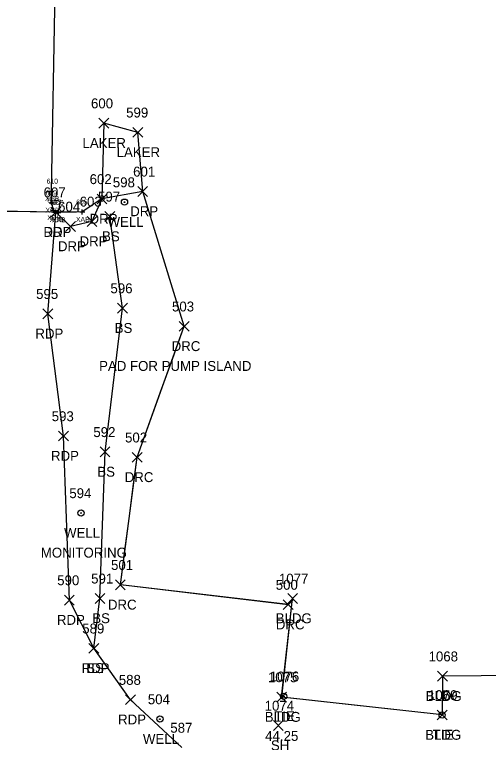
# Model space of a CAD drawing. Extents: x 1715662 to 1717487, y 887396 to 890004.
# Drawn here: x 1716620 to 1716715.7, y 888252.4 to 888399.3 of the extents above; entities that cross this region are included whole.
import ezdxf

# ---------------------------------------------------------------- set-up
doc = ezdxf.new("R2010")
doc.units = 0
for name, color, linetype in [('B_A', 7, 'Continuous'), ('B_I', 7, 'Continuous'), ('B_TIC', 7, 'Continuous'), ('BDC', 7, 'Continuous'), ('BSUBM', 7, 'Continuous'), ('C_A', 7, 'Continuous'), ('C_C', 7, 'Continuous'), ('C_I', 7, 'Continuous'), ('CBP', 7, 'Continuous'), ('L_A', 7, 'Continuous'), ('L_I', 7, 'Continuous'), ('L_TIC', 7, 'Continuous'), ('LAWE', 7, 'Continuous'), ('LBC', 7, 'Continuous'), ('LELB', 7, 'Continuous'), ('LSOGP', 7, 'Continuous'), ('P_A', 7, 'Continuous'), ('P_I', 7, 'Continuous'), ('P_TIC', 7, 'Continuous'), ('PET', 7, 'Continuous'), ('R_A', 7, 'Continuous'), ('R_C', 7, 'Continuous'), ('R_I', 7, 'Continuous'), ('R_TIC', 7, 'Continuous'), ('RDP', 7, 'Continuous'), ('U_A', 7, 'Continuous'), ('U_C', 7, 'Continuous'), ('U_I', 7, 'Continuous'), ('UWW', 7, 'Continuous')]:
    doc.layers.add(name, color=color, linetype=linetype)

msp = doc.modelspace()

# ---------------------------------------------------------------- linework, layer by layer
at = {"layer": 'B_TIC'}
for p, q in [((1716627.47, 888363.71), (1716627.55, 888363.71)), ((1716627.55, 888361.33), (1716627.62, 888361.33)), ((1716627.88, 888359.84), (1716627.96, 888359.84)), ((1716628.39, 888359.45), (1716628.47, 888359.45)), ((1716628.91, 888359.4), (1716628.98, 888359.4)), ((1716633.73, 888359.48), (1716633.8, 888359.48))]:
    msp.add_line(p, q, dxfattribs=at)
for points in [[(1716626.97, 888363.71), (1716627.97, 888363.71)], [(1716627.47, 888363.21), (1716627.47, 888364.21)], [(1716627.55, 888360.83), (1716627.55, 888361.83)], [(1716627.05, 888361.33), (1716628.05, 888361.33)], [(1716627.88, 888359.34), (1716627.88, 888360.34)], [(1716627.38, 888359.84), (1716628.38, 888359.84)], [(1716627.89, 888359.45), (1716628.89, 888359.45)], [(1716628.39, 888358.95), (1716628.39, 888359.95)], [(1716628.4, 888359.4), (1716629.4, 888359.4)], [(1716628.9, 888358.9), (1716628.9, 888359.9)], [(1716633.22, 888359.48), (1716634.22, 888359.48)], [(1716633.72, 888358.98), (1716633.72, 888359.98)]]:
    msp.add_lwpolyline(points, dxfattribs=at)
at = {"layer": 'BDC'}
msp.add_lwpolyline([(1716628.39, 888359.45), (1716627.88, 888359.84), (1716627.55, 888361.33), (1716627.47, 888363.71), (1716628.25, 888404.24), (1716628.98, 888438.57)], dxfattribs=at)
at = {"layer": 'BSUBM'}
msp.add_lwpolyline([(1716633.72, 888359.48), (1716628.9, 888359.4)], dxfattribs=at)
at = {"layer": 'CBP'}
for centre, radius in [((1716674.39, 888261.7), 0.625), ((1716674.39, 888261.7), 0.0833), ((1716706.38, 888257.94), 0.625), ((1716706.38, 888257.94), 0.0833)]:
    msp.add_circle(centre, radius, dxfattribs=at)
at = {"layer": 'L_TIC'}
for points in [[(1716637.05, 888376.41), (1716639.05, 888378.41)], [(1716639.05, 888376.41), (1716637.05, 888378.41)], [(1716643.94, 888374.56), (1716645.94, 888376.56)], [(1716645.94, 888374.56), (1716643.94, 888376.56)], [(1716638.26, 888357.58), (1716640.26, 888359.58)], [(1716640.26, 888357.58), (1716638.26, 888359.58)], [(1716640.82, 888339.07), (1716642.82, 888341.07)], [(1716642.82, 888339.07), (1716640.82, 888341.07)], [(1716637.31, 888310.04), (1716639.31, 888312.04)], [(1716639.31, 888310.04), (1716637.31, 888312.04)], [(1716636.29, 888280.47), (1716638.29, 888282.47)], [(1716638.29, 888280.47), (1716636.29, 888282.47)], [(1716675.19, 888280.45), (1716677.19, 888282.45)], [(1716677.19, 888280.45), (1716675.19, 888282.45)], [(1716635.07, 888270.39), (1716637.07, 888272.39)], [(1716637.07, 888270.39), (1716635.07, 888272.39)], [(1716705.46, 888264.75), (1716707.46, 888266.75)], [(1716707.46, 888264.75), (1716705.46, 888266.75)], [(1716672.97, 888260.55), (1716674.97, 888262.55)], [(1716674.97, 888260.55), (1716672.97, 888262.55)], [(1716705.37, 888256.93), (1716707.37, 888258.93)], [(1716707.37, 888256.93), (1716705.37, 888258.93)], [(1716672.31, 888254.8), (1716674.31, 888256.8)], [(1716674.31, 888254.8), (1716672.31, 888256.8)]]:
    msp.add_lwpolyline(points, dxfattribs=at)
at = {"layer": 'LAWE'}
msp.add_lwpolyline([(1716644.94, 888375.56), (1716638.05, 888377.41)], dxfattribs=at)
at = {"layer": 'LBC'}
msp.add_lwpolyline([(1716706.46, 888265.75), (1716706.37, 888257.93), (1716673.97, 888261.55), (1716676.19, 888281.45)], dxfattribs=at)
at = {"layer": 'LELB'}
msp.add_lwpolyline([(1716636.07, 888271.39), (1716637.29, 888281.47), (1716638.31, 888311.04), (1716641.82, 888340.07), (1716639.26, 888358.58)], dxfattribs=at)
at = {"layer": 'LSOGP'}
msp.add_lwpolyline([(1716722.06, 888265.93), (1716706.46, 888265.74), (1716706.38, 888257.93), (1716673.98, 888261.56), (1716676.19, 888281.45), (1716675.31, 888280.2), (1716666.83, 888281.21), (1716658.35, 888282.21), (1716649.88, 888283.21), (1716641.4, 888284.21), (1716642.25, 888290.65), (1716643.1, 888297.08), (1716643.94, 888303.52), (1716644.79, 888309.95), (1716647.16, 888316.56), (1716649.53, 888323.17), (1716651.9, 888329.79), (1716654.27, 888336.4), (1716645.91, 888363.63), (1716644.94, 888375.56), (1716638.05, 888377.42), (1716637.69, 888362.11), (1716633.72, 888359.48), (1716632.52, 888359.46), (1716631.31, 888359.44), (1716630.11, 888359.42), (1716628.39, 888359.45), (1716620.62, 888359.57), (1716612.85, 888359.69)], dxfattribs=at)
at = {"layer": 'P_TIC'}
for points in [[(1716627.39, 888358.45), (1716629.39, 888360.45)], [(1716629.39, 888358.45), (1716627.39, 888360.45)], [(1716625.75, 888337.93), (1716627.75, 888339.93)], [(1716627.75, 888337.93), (1716625.75, 888339.93)], [(1716628.9, 888313.25), (1716630.9, 888315.25)], [(1716630.9, 888313.25), (1716628.9, 888315.25)], [(1716630.1, 888280.13), (1716632.1, 888282.13)], [(1716632.1, 888280.13), (1716630.1, 888282.13)], [(1716635.07, 888270.39), (1716637.07, 888272.39)], [(1716637.07, 888270.39), (1716635.07, 888272.39)], [(1716642.45, 888260.02), (1716644.45, 888262.02)], [(1716644.45, 888260.02), (1716642.45, 888262.02)]]:
    msp.add_lwpolyline(points, dxfattribs=at)
at = {"layer": 'PET'}
msp.add_lwpolyline([(1716653.85, 888251.35), (1716643.45, 888261.02), (1716636.07, 888271.39), (1716631.1, 888281.13), (1716629.9, 888314.25), (1716626.75, 888338.93), (1716628.39, 888359.45), (1716612.85, 888359.68)], dxfattribs=at)
at = {"layer": 'R_TIC'}
for points in [[(1716644.91, 888362.63), (1716646.91, 888364.63)], [(1716646.91, 888362.63), (1716644.91, 888364.63)], [(1716636.69, 888361.11), (1716638.69, 888363.11)], [(1716638.69, 888361.11), (1716636.69, 888363.11)], [(1716627.39, 888358.45), (1716629.39, 888360.45)], [(1716629.39, 888358.45), (1716627.39, 888360.45)], [(1716630.32, 888355.56), (1716632.32, 888357.56)], [(1716632.32, 888355.56), (1716630.32, 888357.56)], [(1716634.67, 888356.58), (1716636.67, 888358.58)], [(1716636.67, 888356.58), (1716634.67, 888358.58)], [(1716653.27, 888335.4), (1716655.27, 888337.4)], [(1716655.27, 888335.4), (1716653.27, 888337.4)], [(1716643.79, 888308.95), (1716645.79, 888310.95)], [(1716645.79, 888308.95), (1716643.79, 888310.95)], [(1716640.4, 888283.21), (1716642.4, 888285.21)], [(1716642.4, 888283.21), (1716640.4, 888285.21)], [(1716674.31, 888279.21), (1716676.31, 888281.21)], [(1716676.31, 888279.21), (1716674.31, 888281.21)]]:
    msp.add_lwpolyline(points, dxfattribs=at)
at = {"layer": 'RDP'}
for points in [[(1716645.91, 888363.63), (1716637.69, 888362.11), (1716635.67, 888357.58), (1716631.32, 888356.56), (1716628.39, 888359.45)], [(1716675.31, 888280.21), (1716641.4, 888284.21), (1716644.79, 888309.95), (1716654.27, 888336.4)]]:
    msp.add_lwpolyline(points, dxfattribs=at)
at = {"layer": 'UWW'}
for centre, radius in [((1716642.24, 888361.47), 0.625), ((1716642.24, 888361.47), 0.0833), ((1716633.46, 888298.71), 0.625), ((1716633.46, 888298.71), 0.0833), ((1716649.39, 888257.1), 0.625), ((1716649.39, 888257.1), 0.0833)]:
    msp.add_circle(centre, radius, dxfattribs=at)

# ---------------------------------------------------------------- texts
at = {"layer": 'B_A'}
for s, p in [('XCB', (1716626.21, 888361.71)), ('XCB', (1716626.28, 888359.33)), ('XCB', (1716626.62, 888357.84)), ('XCB', (1716627.12, 888357.45)), ('XAB', (1716627.62, 888357.4)), ('XAB', (1716632.44, 888357.48))]:
    msp.add_text(s, height=1, dxfattribs=at).set_placement(p)
at = {"layer": 'B_I'}
for s, p in [('610', (1716626.51, 888365.21)), ('609', (1716626.3, 888362.83)), ('608', (1716626.64, 888361.34)), ('607', (1716627.14, 888360.95)), ('606', (1716627.63, 888360.9)), ('605', (1716632.48, 888360.98))]:
    msp.add_text(s, height=1, dxfattribs=at).set_placement(p)
at = {"layer": 'C_A'}
for p in [(1716672.47, 888256.7), (1716704.46, 888252.94)]:
    msp.add_text('TIE', height=2, dxfattribs=at).set_placement(p)
at = {"layer": 'C_C'}
msp.add_text('44.25', height=2, dxfattribs=at).set_placement((1716670.65, 888252.7))
at = {"layer": 'C_I'}
for s, p in [('1076', (1716671.57, 888264.7)), ('1070', (1716703.52, 888260.94))]:
    msp.add_text(s, height=2, dxfattribs=at).set_placement(p)
at = {"layer": 'L_A'}
for s, p in [('LAKER', (1716633.76, 888372.41)), ('LAKER', (1716640.65, 888370.56)), ('BS', (1716637.71, 888353.58)), ('BS', (1716640.26, 888335.07)), ('BS', (1716636.75, 888306.04)), ('BS', (1716635.73, 888276.47)), ('BLDG', (1716672.78, 888276.45)), ('BS', (1716634.51, 888266.39)), ('BLDG', (1716703.05, 888260.75)), ('BLDG', (1716670.56, 888256.55)), ('BLDG', (1716702.96, 888252.93)), ('SH', (1716671.8, 888250.8))]:
    msp.add_text(s, height=2, dxfattribs=at).set_placement(p)
at = {"layer": 'L_I'}
for s, p in [('600', (1716635.47, 888380.41)), ('599', (1716642.57, 888378.56)), ('597', (1716636.9, 888361.58)), ('596', (1716639.4, 888343.07)), ('592', (1716635.95, 888314.04)), ('591', (1716635.5, 888284.47)), ('1077', (1716673.42, 888284.45)), ('589', (1716633.7, 888274.39)), ('1068', (1716703.64, 888268.75)), ('1075', (1716671.2, 888264.55)), ('1069', (1716703.55, 888260.93)), ('1074', (1716670.54, 888258.8))]:
    msp.add_text(s, height=2, dxfattribs=at).set_placement(p)
at = {"layer": 'P_A'}
for p in [(1716625.87, 888354.45), (1716624.24, 888333.93), (1716627.39, 888309.25), (1716628.59, 888276.13), (1716633.56, 888266.39), (1716640.94, 888256.02)]:
    msp.add_text('RDP', height=2, dxfattribs=at).set_placement(p)
at = {"layer": 'P_I'}
for s, p in [('607', (1716625.9, 888362.45)), ('595', (1716624.39, 888341.93)), ('593', (1716627.54, 888317.25)), ('590', (1716628.65, 888284.13)), ('589', (1716633.7, 888274.39)), ('588', (1716641.09, 888264.02)), ('587', (1716651.49, 888254.35))]:
    msp.add_text(s, height=2, dxfattribs=at).set_placement(p)
at = {"layer": 'R_A'}
for s, p in [('DRP', (1716643.39, 888358.63)), ('DRP', (1716635.18, 888357.11)), ('DRP', (1716625.87, 888354.45)), ('DRP', (1716633.16, 888352.58)), ('DRP', (1716628.8, 888351.56)), ('DRC', (1716651.76, 888331.4)), ('DRC', (1716642.28, 888304.95)), ('DRC', (1716638.89, 888279.21)), ('DRC', (1716672.8, 888275.21))]:
    msp.add_text(s, height=2, dxfattribs=at).set_placement(p)
at = {"layer": 'R_C'}
msp.add_text('PAD FOR PUMP ISLAND', height=2, dxfattribs=at).set_placement((1716637.11, 888327.4))
at = {"layer": 'R_I'}
for s, p in [('601', (1716643.98, 888366.63)), ('602', (1716635.2, 888365.11)), ('607', (1716625.9, 888362.45)), ('603', (1716633.18, 888360.58)), ('604', (1716628.83, 888359.56)), ('503', (1716651.83, 888339.4)), ('502', (1716642.35, 888312.95)), ('501', (1716639.52, 888287.21)), ('500', (1716672.78, 888283.21))]:
    msp.add_text(s, height=2, dxfattribs=at).set_placement(p)
at = {"layer": 'U_A'}
for p in [(1716638.81, 888356.47), (1716630.03, 888293.71), (1716645.96, 888252.1)]:
    msp.add_text('WELL', height=2, dxfattribs=at).set_placement(p)
at = {"layer": 'U_C'}
msp.add_text('MONITORING', height=2, dxfattribs=at).set_placement((1716625.34, 888289.71))
at = {"layer": 'U_I'}
for s, p in [('598', (1716639.88, 888364.47)), ('594', (1716631.1, 888301.71)), ('504', (1716646.95, 888260.1))]:
    msp.add_text(s, height=2, dxfattribs=at).set_placement(p)

doc.saveas('drawing.dxf')
